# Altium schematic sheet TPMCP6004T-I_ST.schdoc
size 127 x 101 mm
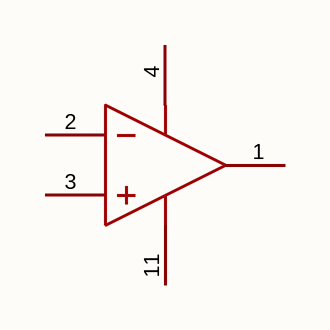
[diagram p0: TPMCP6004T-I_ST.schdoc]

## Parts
U?  tpmcp6004t-i/st  [TSSOP-14_L5.0-W4.4-P0.65-LS6.4-BL]  (value not drawn)  (part A of 4)

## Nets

Not connected (* = marked no-connect by the designer): U? 1(1OUT) 2(1IN−) 3(1IN+) 4(V+) 11(V-)

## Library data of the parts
U? = tpmcp6004t-i/st: 放大器数:2;轨到轨:轨到轨输入,轨到轨输出;增益带宽积(GBW):1MHz;输入失调电压(Vos):5mV;压摆率(SR):-;输入偏置电流(Ib):10pA;; Manufacturer: TECH PUBLIC(台舟); AddInBom: yes; ModelId: 02f1f60386074b2ca8e111040ac061f2; ModelName: TSSOP-14_L5.0-W4.4-H1.0-LS6.4-P0.65; ModelTransform: 237.007,196.85,0,90,0,0,0,0,0; Number of Channels: 2; Maximum Power Supply Range (Vdd-Vss): 5.5V; Gain Bandwidth Product: 1MHz; Vos - Input Offset Voltage: 5mV; Input Offset Voltage Drift(Vos TC): 650nV/℃; Ib - Input Bias Current: 10pA; Common Mode Rejection Ratio(CMRR): 95dB; Quiescent Current: 50uA; Output Current: 20mA; Single supply: 2.1V~5.5V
